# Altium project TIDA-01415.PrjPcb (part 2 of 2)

## Sheet TIDA-01415_page4.SchDoc
size 431 x 279 mm; Date: Not shown in title block; ApprovedBy: Not shown in title block; CheckedBy: Not shown in title block; Author: Not shown in title block; CompanyName: Not shown in title block; DrawnBy: Surya Mishra; Engineer: Not shown in title block; Organization: Not shown in title block; Address1: Not shown in title block; Address2: Not shown in title block; Address3: Not shown in title block; Address4: Not shown in title block; DocumentNumber: 1; Revision: Use project parameter SCH_Rev; SheetNumber: 5; SheetTotal: 6; PageSetup: Record=PageOptions¦CenterHorizontal=True¦CenterVertical=True¦PrintScale=1.00¦XCorrection=1.00¦YCorrection=1.00¦PrintKind=0¦BorderSize=5000000¦LeftOffset=0¦BottomOffset=0¦Orientation=2¦PaperLength=1000¦PaperWidth=1000¦Scale=100¦PaperSource=15¦PrintQuality=600¦MediaType=1¦DitherType=10¦PaperKind=Letter¦PrintScaleMode=1
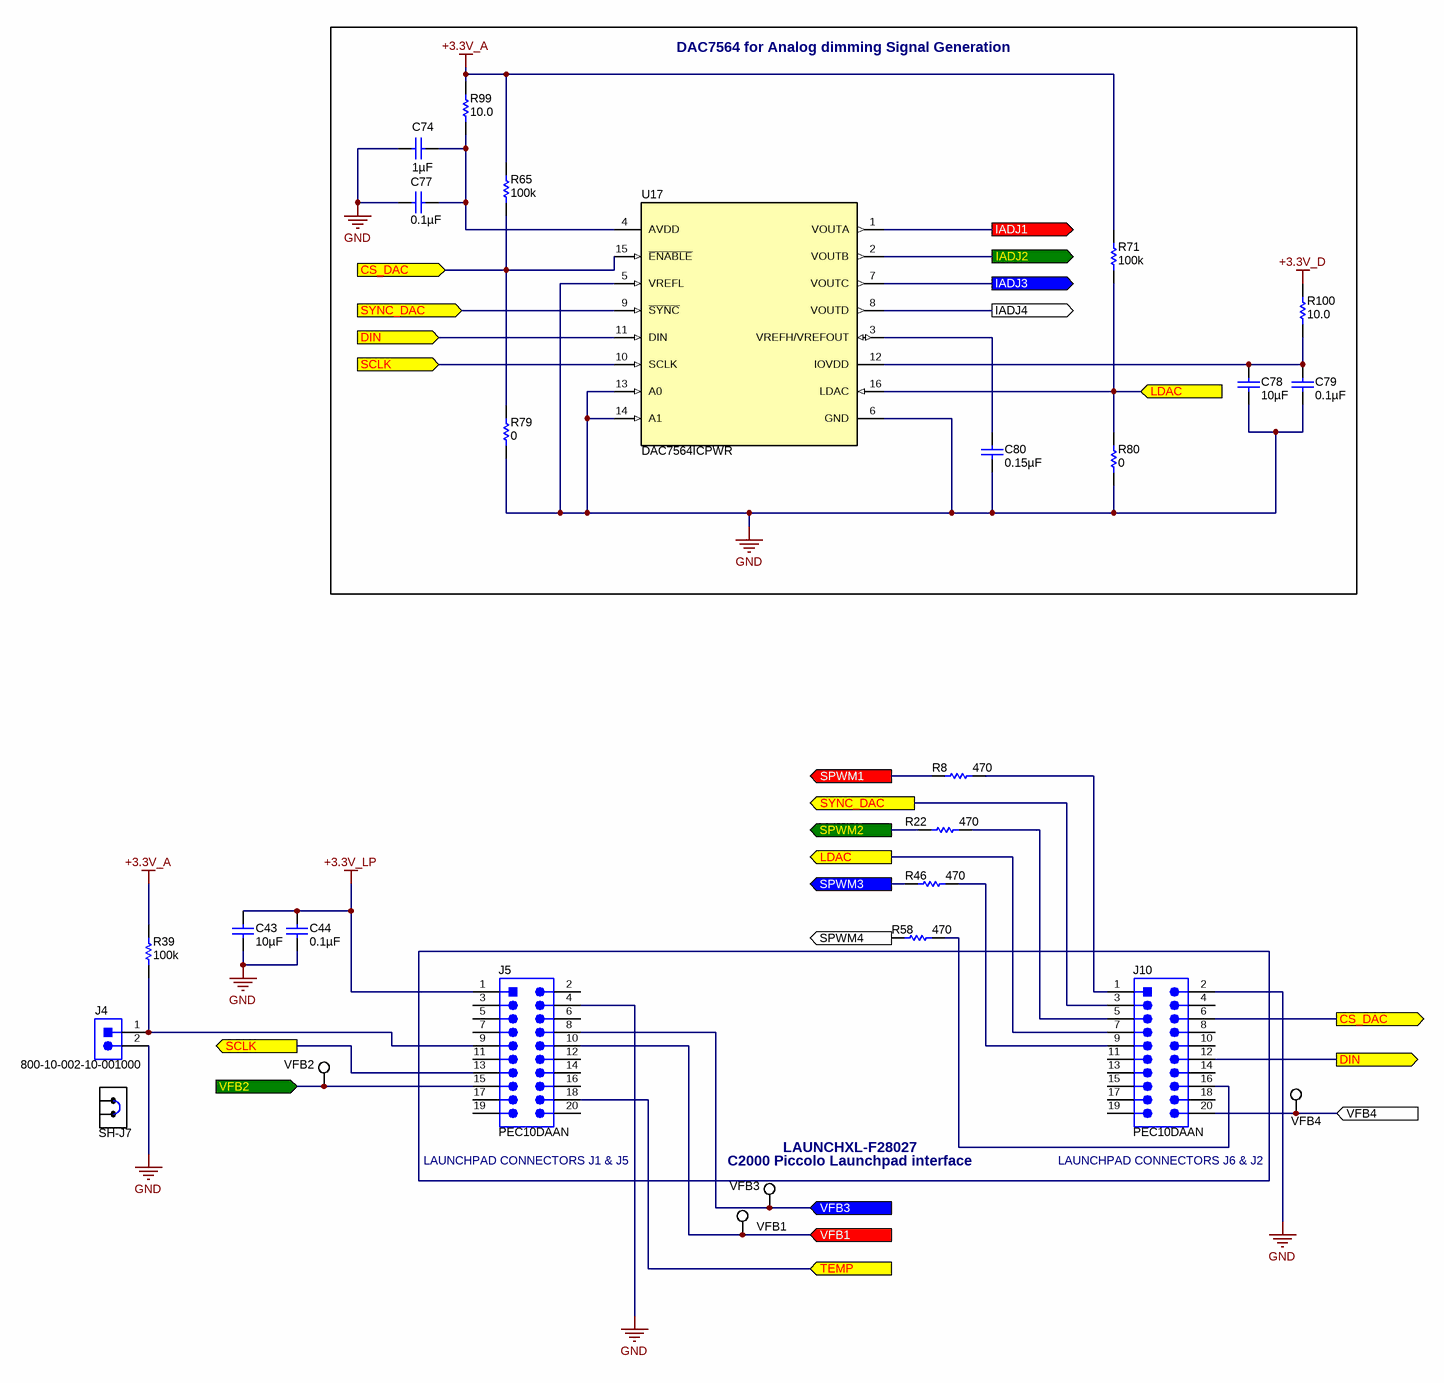
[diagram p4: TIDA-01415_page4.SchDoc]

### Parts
C43  ValueDisplayed: 10µF  [0603]  (hidden comment: GRT188C81A106ME13D)
C44  ValueDisplayed: 0.1µF  [0402]  (hidden comment: GRM155R61A104KA01D)
C74  ValueDisplayed: 1µF  [0603]  (hidden comment: C1608X7R1C105K080AC)
C77  ValueDisplayed: 0.1µF  [0603]  (hidden comment: GRM188R71H104KA93D)
C78  ValueDisplayed: 10µF  [0603]  (hidden comment: GRT188C81A106ME13D)
C79  ValueDisplayed: 0.1µF  [0603]  (hidden comment: GRM188R71H104KA93D)
C80  ValueDisplayed: 0.15µF  [0603]  (hidden comment: C1608X7R1E154K080AA)
J4  800-10-002-10-001000  [Mill-Max_800-10-002-10-001000]
J5  PEC10DAAN  [SULLINS_PEC10DAAN]
J10  PEC10DAAN  [SULLINS_PEC10DAAN]
R8  ValueDisplayed: 470  [0402]  (hidden comment: CRCW0402470RJNED)
R22  ValueDisplayed: 470  [0402]  (hidden comment: CRCW0402470RJNED)
R39  ValueDisplayed: 100k  [0603]  (hidden comment: CRCW0603100KFKEA)
R46  ValueDisplayed: 470  [0402]  (hidden comment: CRCW0402470RJNED)
R58  ValueDisplayed: 470  [0402]  (hidden comment: CRCW0402470RJNED)
R65  ValueDisplayed: 100k  [0603]  (hidden comment: CRCW0603100KFKEA)
R71  ValueDisplayed: 100k  [0603]  (hidden comment: CRCW0603100KFKEA)
R79  ValueDisplayed: 0  [0603]  (hidden comment: CRCW06030000Z0EA)
R80  ValueDisplayed: 0  [0603]  (hidden comment: CRCW06030000Z0EA)
R99  ValueDisplayed: 10.0  [0603]  (hidden comment: CRCW060310R0FKEA)
R100  ValueDisplayed: 10.0  [0603]  (hidden comment: CRCW060310R0FKEA)
SH-J7  969102-0000-DA  [SNT-100-BK-G]  (value not drawn)
U17  DAC7564ICPWR  [PW0016A_N]
VFB1  5015  [Testpoint_Keystone_Miniature]  (value not drawn)
VFB2  5015  [Testpoint_Keystone_Miniature]  (value not drawn)
VFB3  5015  [Testpoint_Keystone_Miniature]  (value not drawn)
VFB4  5015  [Testpoint_Keystone_Miniature]  (value not drawn)

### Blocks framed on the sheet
DAC7564 for Analog dimming Signal Generation: C74 C77-C80 R65 R71 R79 R80 R99 R100 U17

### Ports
CS_DAC (in), CS_DAC (out), DIN (in), DIN (out), IADJ1 (out), IADJ2 (out), IADJ3 (out), IADJ4 (out), LDAC (in), LDAC (out), SCLK (in), SCLK (out), SPWM1 (out), SPWM2 (out), SPWM3 (out), SPWM4 (out), SYNC_DAC (in), SYNC_DAC (out), TEMP (in), VFB1 (in), VFB2 (in), VFB3 (in), VFB4 (in)

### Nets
+3.3V_A: R39.2 R65.2 R71.2 R99.1
+3.3V_D: R100.1
+3.3V_LP: C43.1 C44.2 J5.1
GND: C43.2 C44.1 C74.2 C77.1 C78.2 C79.1 C80.1 J4.2 J5.4 J10.2 R79.1 R80.1 U17.5(VREFL) U17.6(GND) U17.13(A0) U17.14(A1)
CS_DAC: J10.6 R65.1 R79.2 U17.15(~{ENABLE}) ; port CS_DAC
DIN: J10.12 U17.11(DIN) ; port DIN
IADJ1: U17.1(VOUTA) ; port IADJ1
IADJ2: U17.2(VOUTB) ; port IADJ2
IADJ3: U17.7(VOUTC) ; port IADJ3
IADJ4: U17.8(VOUTD) ; port IADJ4
LDAC: J10.7 R71.1 R80.2 U17.16(LDAC) ; port LDAC
SCLK: J5.13 U17.10(SCLK) ; port SCLK
SPWM1: R8.2 ; port SPWM1
SPWM2: R22.2 ; port SPWM2
SPWM3: R46.2 ; port SPWM3
SPWM4: R58.2 ; port SPWM4
SYNC_DAC: J10.3 U17.9(~{SYNC}) ; port SYNC_DAC
TEMP: J5.18 ; port TEMP
VFB1: J5.10 VFB1.1 ; port VFB1
VFB2: J5.15 VFB2.1 ; port VFB2
VFB3: J5.8 VFB3.1 ; port VFB3
VFB4: J10.20 VFB4.1 ; port VFB4
NetC74_1: C74.1 C77.2 R99.2 U17.4(AVDD)
NetC78_1: C78.1 C79.2 R100.2 U17.12(IOVDD)
NetC80_2: C80.2 U17.3(VREFH/VREFOUT)
NetJ4_1: J4.1 J5.9 R39.1
NetJ10_1: J10.1 R8.1
NetJ10_5: J10.5 R22.1
NetJ10_9: J10.9 R46.1
NetJ10_16: J10.16 R58.1

Not connected (* = marked no-connect by the designer): J5 2 3 5 6 7 11 12 14 16 17 19 20; J10 4 8 10 11 13 14 15 17 18 19

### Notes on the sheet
- (near J5) LAUNCHPAD CONNECTORS J1 & J5
- (near VFB3) LAUNCHXL-F28027
- (near VFB3) C2000 Piccolo Launchpad interface
- (near J10) LAUNCHPAD CONNECTORS J6 & J2

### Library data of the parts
C43 C78 = GRT188C81A106ME13D: CAP, CERM, 10 µF, 10 V, +/- 20%, X6S, AEC-Q200 Grade 2, 0603; Manufacturer: MuRata; Polarized: N; CompType: Capacitor; Value: 10uF; U/M: EA; Cap_F: 0.00001; Tolerance_%: 20; Value1: Unknown; VDC_V: 10; Value2: 10V; TaMin_C: -55; TaMax_C: 105; SizeArea_mm2: 1.28; SizeAreaWB_mm2: 4.68; SizeX_mm: 1.6; SizeY_mm: 0.8; SizeZ_mm: 1; AEC Category: Q200; AEC Qualified: Y; AEC Grade: 2
C44 = GRM155R61A104KA01D: CAP, CERM, 0.1 µF, 10 V, +/- 10%, X5R, 0402; Manufacturer: MuRata; Polarized: N; CompType: Capacitor; Value: 0.1uF; U/M: EA; Cap_F: 0.0000001; Tolerance_%: 10; Value1: Unknown; Value2: 10V; TaMin_C: -55; TaMax_C: 85; SizeArea_mm2: 0.5; SizeAreaWB_mm2: 3; SizeX_mm: 1; SizeZ_mm: 0.6; AEC Category: Q200
C74 = C1608X7R1C105K080AC: CAP, CERM, 1 µF, 16 V, +/- 10%, X7R, 0603; Manufacturer: TDK; Polarized: N; CompType: Capacitor; Value: 1uF; U/M: EA; Cap_F: 0.000001; Tolerance_%: 10; ESR_ohm: 0.0057; Value1: 0.0057 ohm; VDC_V: 16; Value2: 16V; TaMin_C: -55; TaMax_C: 125; SizeArea_mm2: 1.28; SizeAreaWB_mm2: 4.68; SizeX_mm: 1.6; SizeY_mm: 0.8; SizeZ_mm: 1; AEC Category: Q200
C77 C79 = GRM188R71H104KA93D: CAP, CERM, 0.1 µF, 50 V, +/- 10%, X7R, 0603; Manufacturer: MuRata; Polarized: N; CompType: Capacitor; Value: 0.1uF; U/M: EA; Cap_F: 0.0000001; Tolerance_%: 10; Value1: Unknown; VDC_V: 50; Value2: 50V; TaMin_C: -55; TaMax_C: 125; SizeArea_mm2: 1.28; SizeAreaWB_mm2: 4.68; SizeX_mm: 1.6; SizeY_mm: 0.8; SizeZ_mm: 1; AEC Category: Q200
C80 = C1608X7R1E154K080AA: CAP, CERM, 0.15 µF, 25 V, +/- 10%, X7R, 0603; Manufacturer: TDK; Polarized: N; CompType: Capacitor; Value: 0.15uF; U/M: EA; Cap_F: 0.00000015; Tolerance_%: 10; Value1: Unknown; VDC_V: 25; Value2: 25V; TaMin_C: -55; TaMax_C: 125; SizeArea_mm2: 1.28; SizeAreaWB_mm2: 4.68; SizeX_mm: 1.6; SizeY_mm: 0.8; SizeZ_mm: 1; AEC Category: Q200
J4 = 800-10-002-10-001000: Header, 100mil, 2x1, TH; Manufacturer: Mill-Max; SymbolCreator: a0412235
J5 J10 = PEC10DAAN: Header, 100mil, 10x2, TH; Manufacturer: Sullins Connector Solutions; SymbolCreator: a0412235
R8 R22 R46 R58 = CRCW0402470RJNED: RES, 470, 5%, 0.063 W, 0402; Manufacturer: Vishay-Dale; CompType: Resistor; Value: 470; Value_Code: 470R; Tolerance_%: 5; Power_W: 0.063; Value2: 0.063W; VDC_V: 50; TempCo: 200 ppm/C; SizeArea_mm2: 0.5; SizeX_mm: 1; SizeZ_mm: 0.6; EIA_Code: E24; U/M: EA; AEC Category: Q200
R39 R65 R71 = CRCW0603100KFKEA: RES, 100 k, 1%, 0.1 W, 0603; Manufacturer: Vishay-Dale; CompType: Resistor; Value: 100k; Res_ohm: 100000; Tolerance_%: 1; Power_W: 0.1; Value2: 0.1W; VDC_V: 75; TempCo: 100 ppm/C; SizeArea_mm2: 1.28; SizeX_mm: 1.6; SizeY_mm: 0.8; EIA_Code: E96; U/M: EA; AEC Category: Q200
R79 R80 = CRCW06030000Z0EA: RES, 0, 5%, 0.1 W, 0603; Manufacturer: Vishay-Dale; CompType: Resistor; Value: 0; Value_Code: 0000; Tolerance_%: 5; Power_W: 0.1; Value2: 0.1W; VDC_V: 75; TempCo: 200 ppm/C; SizeArea_mm2: 1.28; SizeX_mm: 1.6; SizeY_mm: 0.8; SizeZ_mm: 1; EIA_Code: E24; U/M: EA; AEC Category: Q200
R99 R100 = CRCW060310R0FKEA: RES, 10.0, 1%, 0.1 W, 0603; Manufacturer: Vishay-Dale; CompType: Resistor; Value: 10.0; Res_ohm: 10; Value_Code: 10R0; Tolerance_%: 1; Power_W: 0.1; Value2: 0.1W; VDC_V: 75; TempCo: 100 ppm/C; SizeArea_mm2: 1.28; SizeX_mm: 1.6; SizeY_mm: 0.8; EIA_Code: E96; U/M: EA; AEC Category: Q200
SH-J7 = 969102-0000-DA: Shunt, 100mil, Gold plated, Black; Manufacturer: 3M; Alternate Manufacturer: Samtec; Value: 1x2; Note: You can "mate" this to a header by matching the designator.  i.e. use SH-J3 for header J3
U17 = DAC7564ICPWR: 12-Bit, Quad Channel, Ultra-Low Glitch, Voltage Output DAC with 2.5V, 2ppm/degC Internal Reference, PW0016A (TSSOP-16); Manufacturer: Texas Instruments; SymbolCreator: x0208326; SizeArea_mm2: 32; SizeAreaWB_mm2: 58.8; SizeX_mm: 6.4; SizeY_mm: 5; SizeZ_mm: 1.2; CompType: IC; U/M: EA
VFB1-VFB4 = 5015: Test Point, Miniature, SMT; Manufacturer: Keystone; CompType: Test Point Loop

## Sheet TIDA-01415_EVM_Hardware.SchDoc
size 431 x 279 mm; Date: Not shown in title block; ApprovedBy: Not shown in title block; CheckedBy: Not shown in title block; Author: Not shown in title block; CompanyName: Not shown in title block; Engineer: Not shown in title block; Organization: Not shown in title block; Address1: Not shown in title block; Address2: Not shown in title block; Address3: Not shown in title block; Address4: Not shown in title block; DocumentNumber: 1; Revision: Use project parameter SCH_Rev; SheetNumber: 6; SheetTotal: 6; PageSetup: Record=PageOptions¦CenterHorizontal=True¦CenterVertical=True¦PrintScale=1.00¦XCorrection=1.00¦YCorrection=1.00¦PrintKind=0¦BorderSize=5000000¦LeftOffset=0¦BottomOffset=0¦Orientation=2¦PaperLength=1000¦PaperWidth=1000¦Scale=100¦PaperSource=15¦PrintQuality=600¦MediaType=1¦DitherType=10¦PaperKind=Letter¦PrintScaleMode=1
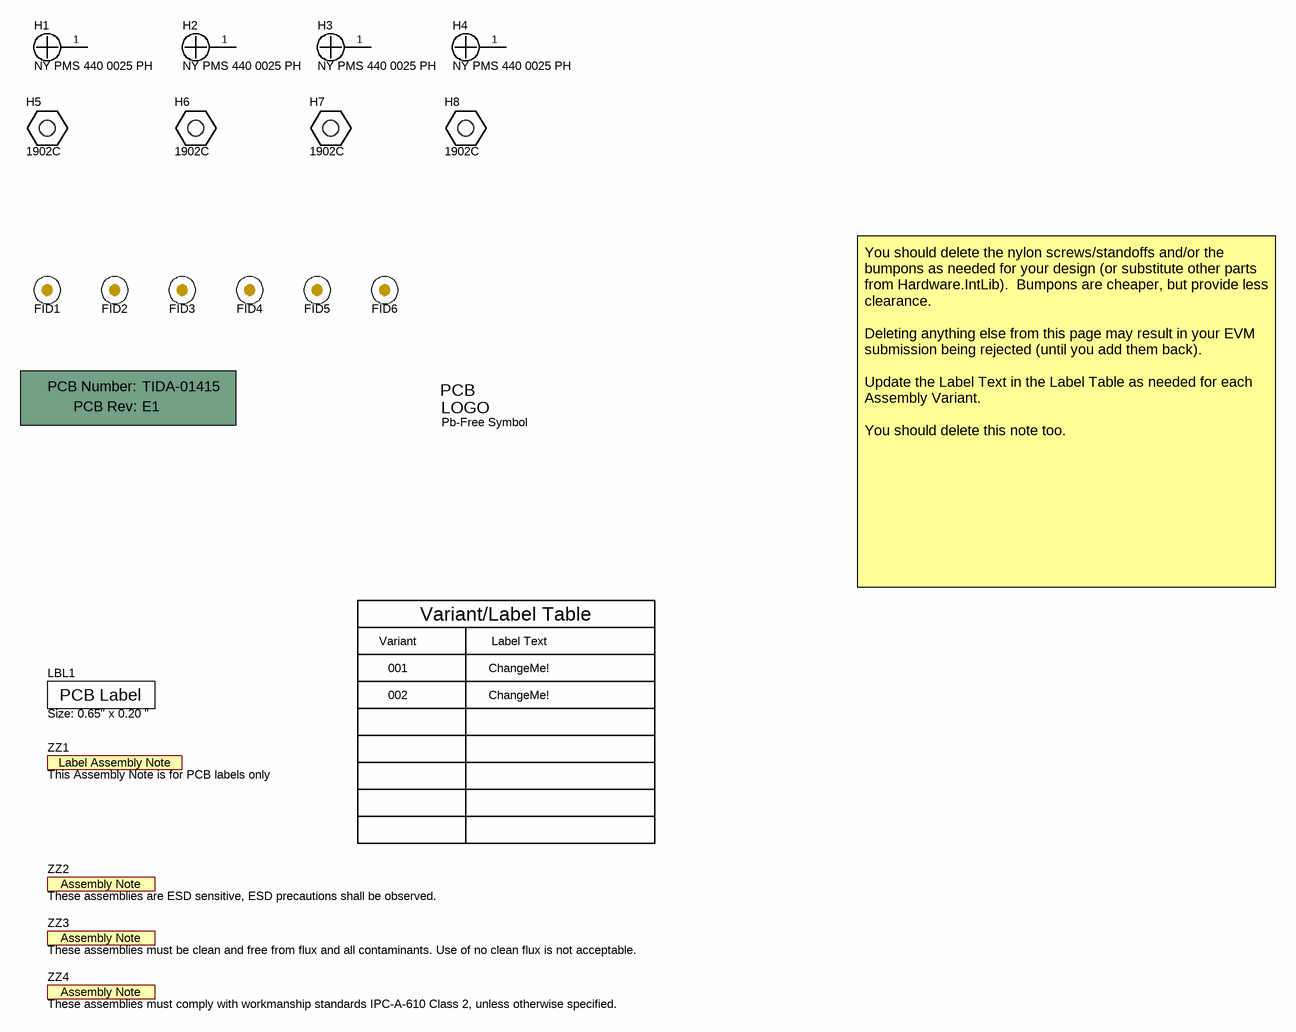
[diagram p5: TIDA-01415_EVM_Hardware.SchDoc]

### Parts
!PCB1  Printed Circuit Board  (value not drawn)  (mechanical)
FID1  Fiducial  [Fiducial10-20]  (value not drawn)
FID2  Fiducial  [Fiducial10-20]  (value not drawn)
FID3  Fiducial  [Fiducial10-20]  (value not drawn)
FID4  Fiducial  [Fiducial10-20]  (value not drawn)
FID5  Fiducial  [Fiducial10-20]  (value not drawn)
FID6  Fiducial  [Fiducial10-20]  (value not drawn)
H1  NY PMS 440 0025 PH  [NY PMS 440 0025 PH]
H2  NY PMS 440 0025 PH  [NY PMS 440 0025 PH]
H3  NY PMS 440 0025 PH  [NY PMS 440 0025 PH]
H4  NY PMS 440 0025 PH  [NY PMS 440 0025 PH]
H5  1902C  [Keystone_1902C]
H6  1902C  [Keystone_1902C]
H7  1902C  [Keystone_1902C]
H8  1902C  [Keystone_1902C]
LBL1  Size: 0.65" x 0.20 "  [Label_650x200]
Logo2  Pb-Free Symbol  [Pb-Free_Overlay_Small]  (no BOM)
ZZ1  This Assembly Note is for PCB labels only  [AssemblyNoteLabel]  (no BOM)
ZZ2  These assemblies are ESD sensitive, ESD precautions shall be observed.  [AssemblyNote]  (no BOM)
ZZ3  These assemblies must be clean and free from flux and all contaminants. Use of no clean flux is not acceptable.  [AssemblyNote]  (no BOM)
ZZ4  These assemblies must comply with workmanship standards IPC-A-610 Class 2, unless otherwise specified.  [AssemblyNote]  (no BOM)

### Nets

Not connected (* = marked no-connect by the designer): H1 1; H2 1; H3 1; H4 1

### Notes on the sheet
- Variant
- Variant/Label Table
- Label Text
- You should delete the nylon screws/standoffs and/or the bumpons as needed for your design (or substitute other parts from Hardware.IntLib).  Bumpons are cheaper, but provide less clearance.
  Deleting anything else from this page may result in your EVM submission being rejected (until you add them back).
  Update the Label Text in the Label Table as needed for each Assembly Variant.
  You should delete this note too.
- 001
- 002
- ChangeMe!

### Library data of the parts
!PCB1 = PCB: Manufacturer: Any; PartNumber: TIDA-01415; SymbolCreator: a0412235
FID1-FID6 = Fiducial: Fiducial mark.  There is nothing to buy or mount.; SymbolCreator: codlsc
H1-H4 = NY PMS 440 0025 PH: Machine Screw, Round, #4-40 x 1/4, Nylon, Philips panhead; Manufacturer: B&F Fastener Supply; CompType: Hardware; SymbolCreator: codlsc; U/M: EA
H5-H8 = 1902C: Standoff, Hex, 0.5"L #4-40 Nylon; Manufacturer: Keystone; CompType: Hardware
LBL1 = THT-14-423-10: Thermal Transfer Printable Labels, 0.650" W x 0.200" H - 10,000 per roll; Manufacturer: Brady; SymbolCreator: a0412235; CompType: Label
Logo2 = Pb-Free: SymbolCreator: a0412235
ZZ1 = AssemblyNoteLabel: SymbolCreator: a0412235
ZZ2-ZZ4 = AssemblyNote: SymbolCreator: codlsc

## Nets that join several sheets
+3.3V_A: TIDA-01415_page3 (C31.1 L5.2 R32.2), TIDA-01415_page4 (R39.2 R65.2 R71.2 R99.1)
+3.3V_D: TIDA-01415_page3 (C102.1 L10.2), TIDA-01415_page4 (R100.1)
+3.3V_LP: TIDA-01415_page3 (C36.1 L6.2), TIDA-01415_page4 (C43.1 C44.2 J5.1)
+10V: TIDA-01415_Page1 (6 pins), TIDA-01415_page3 (5 pins), TIDA-01415_Page2 (6 pins)
GND: TIDA-01415_page3 (38 pins), TIDA-01415_Page2 (R16.2), TIDA-01415_page4 (16 pins)
GND1: TIDA-01415_Page1 (41 pins), TIDA-01415_Page2 (43 pins)
VIN_LED: TIDA-01415_Page1 (17 pins), TIDA-01415_Page2 (19 pins)
VIN_PS: TIDA-01415_page3 (6 pins), TIDA-01415_Page2 (R15.2)
BLED+: TIDA-01415_page3 (R49.2), TIDA-01415_Page2 (10 pins)
GLED+: TIDA-01415_Page1 (10 pins), TIDA-01415_page3 (R25.2)
IADJ1: TIDA-01415_Page1 (R94.2), TIDA-01415_page4 (U17.1)
IADJ2: TIDA-01415_Page1 (R95.2), TIDA-01415_page4 (U17.2)
IADJ3: TIDA-01415_Page2 (R96.2), TIDA-01415_page4 (U17.7)
IADJ4: TIDA-01415_Page2 (R97.2), TIDA-01415_page4 (U17.8)
PWM1: TIDA-01415_Page1 (PWM1.1 R7.2 R86.1 U2.3), TIDA-01415_page3 (J1.1)
PWM2: TIDA-01415_Page1 (PWM2.1 R20.2 R87.1 U5.3), TIDA-01415_page3 (J6.1)
PWM3: TIDA-01415_page3 (J8.1), TIDA-01415_Page2 (PWM3.1 R44.2 R88.1 U11.3)
PWM4: TIDA-01415_page3 (J12.1), TIDA-01415_Page2 (PWM4.1 R56.2 R89.1 U14.3)
RLED+: TIDA-01415_Page1 (10 pins), TIDA-01415_page3 (R12.2)
SHPWM1: TIDA-01415_Page1 (C97.1 R6.2 SH1.1 U1.6), TIDA-01415_page3 (J1.3)
SHPWM2: TIDA-01415_Page1 (C98.1 R21.2 SH2.1 U4.6), TIDA-01415_page3 (J6.3)
SHPWM3: TIDA-01415_page3 (J8.3), TIDA-01415_Page2 (C99.1 R45.2 SH3.1 U10.6)
SHPWM4: TIDA-01415_page3 (J12.3), TIDA-01415_Page2 (C100.1 R57.2 SH4.1 U13.6)
SPWM1: TIDA-01415_page3 (J1.2), TIDA-01415_page4 (R8.2)
SPWM2: TIDA-01415_page3 (J6.2), TIDA-01415_page4 (R22.2)
SPWM3: TIDA-01415_page3 (J8.2), TIDA-01415_page4 (R46.2)
SPWM4: TIDA-01415_page3 (J12.2), TIDA-01415_page4 (R58.2)
TEMP: TIDA-01415_page3 (C39.1 R35.1), TIDA-01415_page4 (J5.18)
UVLO: TIDA-01415_Page1 (R1.2 R2.2 U2.1 U5.1), TIDA-01415_Page2 (U11.1 U14.1)
VFB1: TIDA-01415_page3 (C85.2 R12.1 R14.2), TIDA-01415_page4 (J5.10 VFB1.1)
VFB2: TIDA-01415_page3 (C86.2 R25.1 R28.2), TIDA-01415_page4 (J5.15 VFB2.1)
VFB3: TIDA-01415_page3 (C87.2 R49.1 R52.2), TIDA-01415_page4 (J5.8 VFB3.1)
VFB4: TIDA-01415_page3 (C88.2 R61.1 R64.2), TIDA-01415_page4 (J10.20 VFB4.1)
WLED+: TIDA-01415_page3 (R61.2), TIDA-01415_Page2 (10 pins)

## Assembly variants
001: not fitted C6 C19 C33 C50 C63 C97 C98 C99 C100 FID1 FID2 FID3 R79 R80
